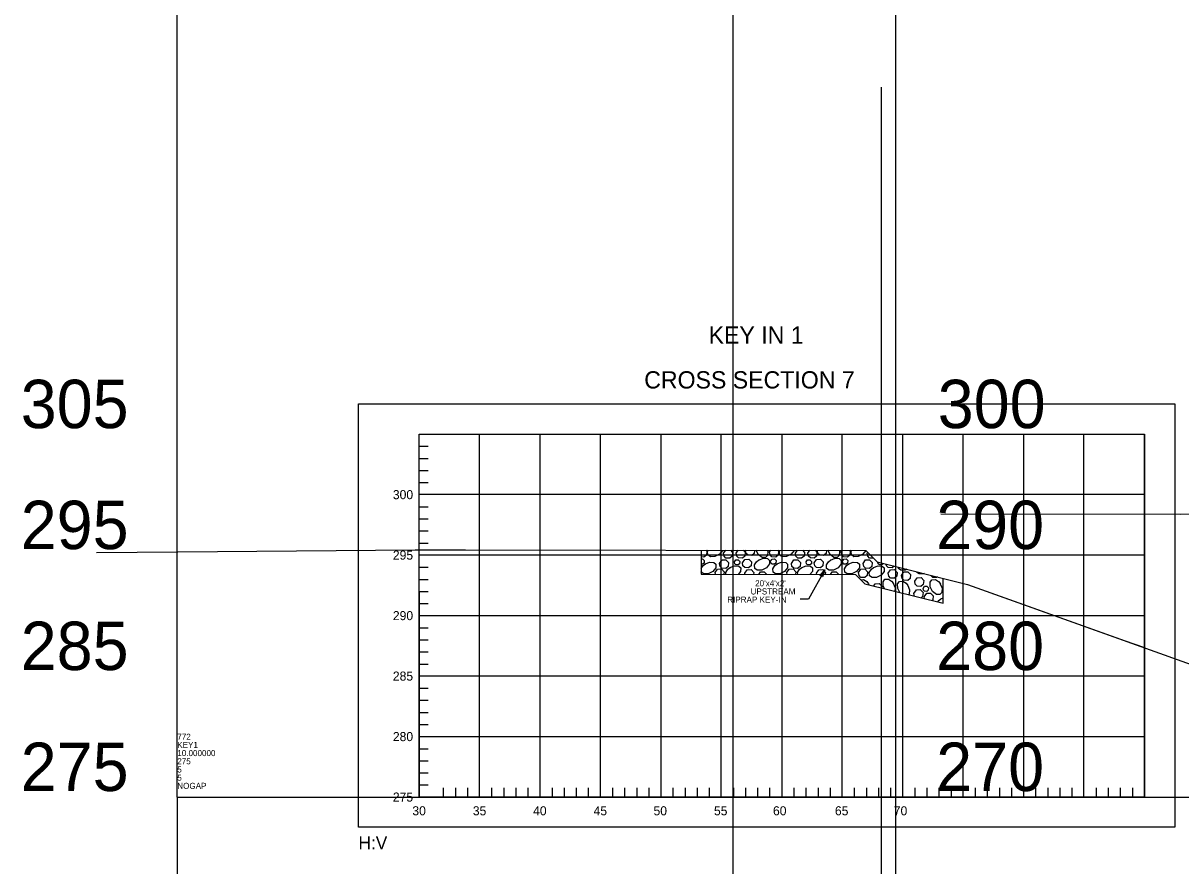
# Model space of a CAD drawing. Extents: x 1578769 to 1579225, y 724002 to 724828.
# Drawn here: x 1578769 to 1578864.8, y 724572.8 to 724642.4 of the extents above; entities that cross this region are included whole.
import ezdxf

# ---------------------------------------------------------------- set-up
doc = ezdxf.new("R2010")
doc.units = 0
for name, color, linetype in [('1', 7, 'Continuous'), ('Default', 7, 'Continuous'), ('Old_Level_1', 7, 'Continuous'), ('Old_Level_41', 7, 'Continuous'), ('Old_Level_42', 7, 'Continuous'), ('R_Exist Surface', 7, 'Continuous'), ('R_Rip-Rap', 7, 'Continuous')]:
    doc.layers.add(name, color=color, linetype=linetype)

msp = doc.modelspace()

# ---------------------------------------------------------------- linework, layer by layer
at = {"layer": '1'}
msp.add_lwpolyline([(1578835.361, 724597.228), (1578833.993, 724594.815), (1578833.307, 724594.815)], dxfattribs=at)
msp.add_lwpolyline([(1578834.961, 724596.765), (1578835.361, 724597.228), (1578835.169, 724596.647)], close=True, dxfattribs=at)
at = {"layer": 'Default'}
for p, q in [((1578781.789, 724578.446), (1578781.789, 724828.446)), ((1578827.766, 724526.976), (1578827.766, 724776.976)), ((1578841.23, 724437.474), (1578841.23, 724687.474)), ((1578840.032, 724387.146), (1578840.032, 724637.146)), ((1578781.789, 724578.446), (1579181.789, 724578.446)), ((1578781.789, 724578.446), (1578781.789, 724328.446))]:
    msp.add_line(p, q, dxfattribs=at)
for points in [[(1578844.95, 724601.856), (1578864.79, 724601.82), (1578874, 724601.865), (1578902.82, 724601.997), (1578906.13, 724598.744), (1578911.44, 724592.793), (1578933.27, 724587.55), (1578934.65, 724587.226), (1578938.86, 724587.197), (1578969.36, 724586.771), (1578979.71, 724588.647), (1578991.4, 724590.556), (1579015.95, 724592.584), (1579047.41, 724595.203), (1579094.57, 724597.518), (1579101.48, 724597.856)], [(1578775.119, 724598.673), (1578781.839, 724598.732), (1578801.469, 724598.898), (1578805.619, 724598.891), (1578838.739, 724598.843), (1578839.679, 724597.89), (1578847.149, 724596.028), (1578873.219, 724586.714), (1578900.509, 724586.288), (1578923.389, 724585.936), (1579003.989, 724586.195), (1579031.649, 724586.167)]]:
    msp.add_lwpolyline(points, dxfattribs=at)
at = {"layer": 'Old_Level_1'}
for points in [[(1578796.789, 724610.946), (1578864.289, 724610.946), (1578864.289, 724575.946), (1578796.789, 724575.946)], [(1578801.789, 724608.446), (1578861.789, 724608.446), (1578861.789, 724578.446), (1578801.789, 724578.446)]]:
    msp.add_lwpolyline(points, close=True, dxfattribs=at)
at = {"layer": 'Old_Level_41'}
for p, q in [((1578806.789, 724578.446), (1578806.789, 724608.446)), ((1578811.789, 724608.446), (1578811.789, 724578.446)), ((1578816.789, 724578.446), (1578816.789, 724608.446)), ((1578821.789, 724608.446), (1578821.789, 724578.446)), ((1578826.789, 724578.446), (1578826.789, 724608.446)), ((1578831.789, 724608.446), (1578831.789, 724578.446)), ((1578836.789, 724578.446), (1578836.789, 724608.446)), ((1578841.789, 724608.446), (1578841.789, 724578.446)), ((1578846.789, 724578.446), (1578846.789, 724608.446)), ((1578851.789, 724608.446), (1578851.789, 724578.446)), ((1578856.789, 724578.446), (1578856.789, 724608.446)), ((1578861.789, 724578.446), (1578861.789, 724608.446)), ((1578801.789, 724595.446), (1578801.789, 724578.446))]:
    msp.add_line(p, q, dxfattribs=at)
for points in [[(1578861.789, 724603.446), (1578801.789, 724603.446)], [(1578861.789, 724598.446), (1578801.789, 724598.446)], [(1578801.789, 724593.446), (1578861.789, 724593.446)], [(1578861.789, 724588.446), (1578801.789, 724588.446)], [(1578801.789, 724583.446), (1578861.789, 724583.446)]]:
    msp.add_lwpolyline(points, dxfattribs=at)
at = {"layer": 'Old_Level_42'}
for p, q in [((1578801.789, 724607.446), (1578802.539, 724607.446)), ((1578801.789, 724606.446), (1578802.539, 724606.446)), ((1578801.789, 724605.446), (1578802.539, 724605.446)), ((1578801.789, 724604.446), (1578802.539, 724604.446)), ((1578801.789, 724602.446), (1578802.539, 724602.446)), ((1578801.789, 724601.446), (1578802.539, 724601.446)), ((1578801.789, 724600.446), (1578802.539, 724600.446)), ((1578801.789, 724599.446), (1578802.539, 724599.446)), ((1578801.789, 724597.446), (1578802.539, 724597.446)), ((1578801.789, 724596.446), (1578802.539, 724596.446)), ((1578801.789, 724595.446), (1578802.539, 724595.446)), ((1578801.789, 724594.446), (1578802.539, 724594.446)), ((1578801.789, 724592.446), (1578802.539, 724592.446)), ((1578801.789, 724591.446), (1578802.539, 724591.446)), ((1578801.789, 724590.446), (1578802.539, 724590.446)), ((1578801.789, 724589.446), (1578802.539, 724589.446)), ((1578801.789, 724587.446), (1578802.539, 724587.446)), ((1578801.789, 724586.446), (1578802.539, 724586.446)), ((1578801.789, 724585.446), (1578802.539, 724585.446)), ((1578801.789, 724584.446), (1578802.539, 724584.446)), ((1578801.789, 724582.446), (1578802.539, 724582.446)), ((1578801.789, 724581.446), (1578802.539, 724581.446)), ((1578801.789, 724580.446), (1578802.539, 724580.446)), ((1578801.789, 724579.446), (1578802.539, 724579.446)), ((1578803.789, 724579.196), (1578803.789, 724578.446)), ((1578804.789, 724579.196), (1578804.789, 724578.446)), ((1578805.789, 724579.196), (1578805.789, 724578.446)), ((1578807.789, 724579.196), (1578807.789, 724578.446)), ((1578808.789, 724579.196), (1578808.789, 724578.446)), ((1578809.789, 724579.196), (1578809.789, 724578.446)), ((1578810.789, 724579.196), (1578810.789, 724578.446)), ((1578812.789, 724579.196), (1578812.789, 724578.446)), ((1578813.789, 724579.196), (1578813.789, 724578.446)), ((1578814.789, 724579.196), (1578814.789, 724578.446)), ((1578815.789, 724579.196), (1578815.789, 724578.446)), ((1578817.789, 724579.196), (1578817.789, 724578.446)), ((1578818.789, 724579.196), (1578818.789, 724578.446)), ((1578819.789, 724579.196), (1578819.789, 724578.446)), ((1578820.789, 724579.196), (1578820.789, 724578.446)), ((1578822.789, 724579.196), (1578822.789, 724578.446)), ((1578823.789, 724579.196), (1578823.789, 724578.446)), ((1578824.789, 724579.196), (1578824.789, 724578.446)), ((1578825.789, 724579.196), (1578825.789, 724578.446)), ((1578827.789, 724579.196), (1578827.789, 724578.446)), ((1578828.789, 724579.196), (1578828.789, 724578.446)), ((1578829.789, 724579.196), (1578829.789, 724578.446)), ((1578830.789, 724579.196), (1578830.789, 724578.446)), ((1578832.789, 724579.196), (1578832.789, 724578.446)), ((1578833.789, 724579.196), (1578833.789, 724578.446)), ((1578834.789, 724579.196), (1578834.789, 724578.446)), ((1578835.789, 724579.196), (1578835.789, 724578.446)), ((1578837.789, 724579.196), (1578837.789, 724578.446)), ((1578838.789, 724579.196), (1578838.789, 724578.446)), ((1578839.789, 724579.196), (1578839.789, 724578.446)), ((1578840.789, 724579.196), (1578840.789, 724578.446)), ((1578842.789, 724579.196), (1578842.789, 724578.446)), ((1578843.789, 724579.196), (1578843.789, 724578.446)), ((1578844.789, 724579.196), (1578844.789, 724578.446)), ((1578845.789, 724579.196), (1578845.789, 724578.446)), ((1578847.789, 724579.196), (1578847.789, 724578.446)), ((1578848.789, 724579.196), (1578848.789, 724578.446)), ((1578849.789, 724579.196), (1578849.789, 724578.446)), ((1578850.789, 724579.196), (1578850.789, 724578.446)), ((1578852.789, 724579.196), (1578852.789, 724578.446)), ((1578853.789, 724579.196), (1578853.789, 724578.446)), ((1578854.789, 724579.196), (1578854.789, 724578.446)), ((1578855.789, 724579.196), (1578855.789, 724578.446)), ((1578857.789, 724579.196), (1578857.789, 724578.446)), ((1578858.789, 724579.196), (1578858.789, 724578.446)), ((1578859.789, 724579.196), (1578859.789, 724578.446)), ((1578860.789, 724579.196), (1578860.789, 724578.446))]:
    msp.add_line(p, q, dxfattribs=at)
at = {"layer": 'R_Exist Surface'}
msp.add_lwpolyline([(1578801.789, 724598.897), (1578805.619, 724598.891), (1578838.739, 724598.843), (1578839.679, 724597.89), (1578847.149, 724596.028), (1578860.184, 724591.371), (1578861.789, 724590.797)], dxfattribs=at)
at = {"layer": 'R_Rip-Rap'}
for p, q in [((1578825.129, 724598.863), (1578825.129, 724596.863)), ((1578826.978, 724598.603), (1578827.159, 724598.86)), ((1578828.019, 724598.615), (1578828.19, 724598.858)), ((1578828.801, 724598.825), (1578828.824, 724598.857)), ((1578830.774, 724598.709), (1578830.876, 724598.854)), ((1578832.914, 724598.603), (1578833.089, 724598.851)), ((1578833.955, 724598.615), (1578834.12, 724598.85)), ((1578834.737, 724598.825), (1578834.754, 724598.849)), ((1578836.71, 724598.709), (1578836.806, 724598.846)), ((1578838.851, 724598.603), (1578838.903, 724598.677)), ((1578826.296, 724596.861), (1578826.268, 724597.004)), ((1578828.74, 724596.858), (1578828.722, 724596.948)), ((1578832.234, 724596.852), (1578832.204, 724597.004)), ((1578834.678, 724596.849), (1578834.658, 724596.948)), ((1578845.129, 724594.47), (1578845.129, 724596.531)), ((1578838.964, 724596.082), (1578838.997, 724595.999)), ((1578842.772, 724595.058), (1578842.727, 724595.288)), ((1578843.609, 724594.849), (1578843.579, 724595.003)), ((1578844.945, 724594.835), (1578845.129, 724594.908))]:
    msp.add_line(p, q, dxfattribs=at)
for points in [[(1578825.509, 724598.862), (1578825.586, 724598.783), (1578825.553, 724598.457), (1578825.354, 724598.292), (1578825.129, 724598.308)], [(1578826.885, 724598.86), (1578826.885, 724598.834), (1578826.635, 724598.514), (1578826.248, 724598.321), (1578825.884, 724598.314), (1578825.679, 724598.46), (1578825.66, 724598.75), (1578825.731, 724598.862)], [(1578827.549, 724598.859), (1578827.726, 724598.676), (1578827.694, 724598.351), (1578827.495, 724598.186), (1578827.177, 724598.209), (1578827.027, 724598.354), (1578826.979, 724598.603)], [(1578828.603, 724598.858), (1578828.766, 724598.688), (1578828.734, 724598.363), (1578828.535, 724598.197), (1578828.217, 724598.22), (1578828.068, 724598.366), (1578828.019, 724598.615)], [(1578829.545, 724598.856), (1578829.516, 724598.573), (1578829.317, 724598.408), (1578828.999, 724598.431), (1578828.85, 724598.576), (1578828.801, 724598.825)], [(1578830.594, 724598.855), (1578830.633, 724598.755), (1578830.603, 724598.409), (1578830.447, 724598.244), (1578830.166, 724598.249), (1578829.846, 724598.499), (1578829.668, 724598.856)], [(1578831.453, 724598.854), (1578831.522, 724598.783), (1578831.489, 724598.457), (1578831.291, 724598.292), (1578830.973, 724598.315), (1578830.823, 724598.46), (1578830.775, 724598.709)], [(1578832.821, 724598.852), (1578832.821, 724598.834), (1578832.571, 724598.514), (1578832.184, 724598.321), (1578831.82, 724598.314), (1578831.615, 724598.46), (1578831.596, 724598.75), (1578831.662, 724598.853)], [(1578833.494, 724598.851), (1578833.662, 724598.676), (1578833.63, 724598.351), (1578833.431, 724598.186), (1578833.113, 724598.209), (1578832.963, 724598.354), (1578832.915, 724598.603)], [(1578834.547, 724598.849), (1578834.703, 724598.688), (1578834.67, 724598.363), (1578834.471, 724598.197), (1578834.153, 724598.22), (1578834.004, 724598.366), (1578833.955, 724598.615)], [(1578835.48, 724598.848), (1578835.452, 724598.573), (1578835.253, 724598.408), (1578834.936, 724598.431), (1578834.786, 724598.576), (1578834.737, 724598.825)], [(1578836.533, 724598.846), (1578836.569, 724598.755), (1578836.539, 724598.409), (1578836.383, 724598.244), (1578836.102, 724598.249), (1578835.782, 724598.499), (1578835.608, 724598.848)], [(1578837.398, 724598.845), (1578837.458, 724598.783), (1578837.426, 724598.457), (1578837.227, 724598.292), (1578836.909, 724598.315), (1578836.759, 724598.46), (1578836.711, 724598.709)], [(1578838.753, 724598.829), (1578838.507, 724598.514), (1578838.12, 724598.321), (1578837.756, 724598.314), (1578837.551, 724598.46), (1578837.532, 724598.75), (1578837.593, 724598.845)], [(1578839.378, 724598.195), (1578839.367, 724598.186), (1578839.049, 724598.209), (1578838.899, 724598.354), (1578838.851, 724598.603)], [(1578825.129, 724598.124), (1578825.244, 724598.13), (1578825.379, 724597.991), (1578825.359, 724597.796), (1578825.24, 724597.697), (1578825.129, 724597.705)], [(1578825.453, 724597.726), (1578825.83, 724597.876), (1578826.177, 724597.846), (1578826.341, 724597.689), (1578826.336, 724597.408), (1578826.086, 724597.088), (1578825.7, 724596.895), (1578825.336, 724596.889), (1578825.131, 724597.035), (1578825.129, 724597.057)], [(1578825.129, 724597.353), (1578825.277, 724597.584), (1578825.468, 724597.736)], [(1578826.648, 724597.763), (1578826.849, 724598.05), (1578827.171, 724598.068), (1578827.395, 724597.836), (1578827.363, 724597.511), (1578827.164, 724597.346), (1578826.846, 724597.369), (1578826.696, 724597.514), (1578826.648, 724597.763)], [(1578827.172, 724596.86), (1578827.161, 724597.02), (1578827.327, 724597.279), (1578827.518, 724597.431)], [(1578827.502, 724597.421), (1578827.88, 724597.571), (1578828.226, 724597.541), (1578828.391, 724597.384), (1578828.386, 724597.103), (1578828.194, 724596.858)], [(1578827.871, 724597.881), (1578827.992, 724598.053), (1578828.186, 724598.064), (1578828.32, 724597.925), (1578828.3, 724597.73), (1578828.181, 724597.631), (1578827.99, 724597.644), (1578827.901, 724597.731), (1578827.871, 724597.881)], [(1578828.532, 724597.807), (1578828.734, 724598.094), (1578829.056, 724598.112), (1578829.28, 724597.88), (1578829.247, 724597.555), (1578829.048, 724597.389), (1578828.731, 724597.412), (1578828.581, 724597.557), (1578828.532, 724597.807)], [(1578829.886, 724598.036), (1578830.263, 724598.186), (1578830.61, 724598.156), (1578830.774, 724597.999), (1578830.769, 724597.718), (1578830.519, 724597.398), (1578830.133, 724597.205), (1578829.768, 724597.199), (1578829.564, 724597.344), (1578829.544, 724597.634), (1578829.71, 724597.894), (1578829.901, 724598.046)], [(1578830.866, 724597.947), (1578830.987, 724598.119), (1578831.18, 724598.13), (1578831.315, 724597.991), (1578831.295, 724597.796), (1578831.176, 724597.697), (1578830.985, 724597.71), (1578830.895, 724597.798), (1578830.866, 724597.947)], [(1578831.389, 724597.726), (1578831.766, 724597.876), (1578832.113, 724597.846), (1578832.277, 724597.689), (1578832.272, 724597.408), (1578832.022, 724597.088), (1578831.636, 724596.895), (1578831.272, 724596.889), (1578831.067, 724597.035), (1578831.047, 724597.325), (1578831.214, 724597.584), (1578831.404, 724597.736)], [(1578832.584, 724597.763), (1578832.785, 724598.05), (1578833.107, 724598.068), (1578833.331, 724597.836), (1578833.299, 724597.511), (1578833.1, 724597.346), (1578832.782, 724597.369), (1578832.632, 724597.514), (1578832.584, 724597.763)], [(1578833.108, 724596.851), (1578833.097, 724597.02), (1578833.263, 724597.279), (1578833.454, 724597.431)], [(1578833.439, 724597.421), (1578833.816, 724597.571), (1578834.162, 724597.541), (1578834.327, 724597.384), (1578834.322, 724597.103), (1578834.124, 724596.85)], [(1578833.807, 724597.881), (1578833.928, 724598.053), (1578834.122, 724598.064), (1578834.256, 724597.925), (1578834.237, 724597.73), (1578834.117, 724597.631), (1578833.926, 724597.644), (1578833.837, 724597.731), (1578833.808, 724597.881)], [(1578834.468, 724597.807), (1578834.67, 724598.094), (1578834.992, 724598.112), (1578835.216, 724597.88), (1578835.183, 724597.555), (1578834.985, 724597.389), (1578834.667, 724597.412), (1578834.517, 724597.557), (1578834.469, 724597.807)], [(1578835.822, 724598.036), (1578836.199, 724598.186), (1578836.546, 724598.156), (1578836.71, 724597.999), (1578836.705, 724597.718), (1578836.455, 724597.398), (1578836.069, 724597.205), (1578835.705, 724597.199), (1578835.5, 724597.344), (1578835.48, 724597.634), (1578835.647, 724597.894), (1578835.837, 724598.046)], [(1578836.802, 724597.947), (1578836.923, 724598.119), (1578837.117, 724598.13), (1578837.251, 724597.991), (1578837.231, 724597.796), (1578837.112, 724597.697), (1578836.921, 724597.71), (1578836.832, 724597.798), (1578836.802, 724597.947)], [(1578837.325, 724597.726), (1578837.702, 724597.876), (1578838.049, 724597.846), (1578838.213, 724597.689), (1578838.208, 724597.408), (1578837.958, 724597.088), (1578837.572, 724596.895), (1578837.208, 724596.889), (1578837.003, 724597.035), (1578836.983, 724597.325), (1578837.15, 724597.584), (1578837.34, 724597.736)], [(1578838.52, 724597.763), (1578838.722, 724598.05), (1578839.043, 724598.068), (1578839.267, 724597.836), (1578839.235, 724597.511), (1578839.036, 724597.346), (1578838.718, 724597.369), (1578838.569, 724597.514), (1578838.52, 724597.763)], [(1578839.375, 724597.421), (1578839.752, 724597.571), (1578840.099, 724597.541), (1578840.263, 724597.384), (1578840.258, 724597.103), (1578840.008, 724596.783), (1578839.622, 724596.59), (1578839.257, 724596.584), (1578839.052, 724596.729), (1578839.033, 724597.02), (1578839.199, 724597.279), (1578839.39, 724597.431)], [(1578840.176, 724597.766), (1578840.173, 724597.73), (1578840.053, 724597.631), (1578839.862, 724597.644), (1578839.773, 724597.731), (1578839.745, 724597.873)], [(1578841.097, 724597.536), (1578840.921, 724597.389), (1578840.603, 724597.412), (1578840.453, 724597.557), (1578840.425, 724597.704)], [(1578842.145, 724597.275), (1578842.005, 724597.205), (1578841.641, 724597.199), (1578841.436, 724597.344), (1578841.428, 724597.454)], [(1578825.129, 724596.863), (1578837.901, 724596.844), (1578838.65, 724596.085), (1578845.129, 724594.47)], [(1578826.268, 724597.004), (1578826.47, 724597.291), (1578826.792, 724597.309), (1578827.016, 724597.077), (1578826.994, 724596.86)], [(1578828.722, 724596.948), (1578828.924, 724597.235), (1578829.246, 724597.253), (1578829.47, 724597.021), (1578829.453, 724596.857)], [(1578829.884, 724596.856), (1578830.026, 724597.059), (1578830.348, 724597.077), (1578830.563, 724596.855)], [(1578832.204, 724597.004), (1578832.406, 724597.291), (1578832.728, 724597.309), (1578832.952, 724597.077), (1578832.929, 724596.851)], [(1578834.658, 724596.948), (1578834.86, 724597.235), (1578835.182, 724597.253), (1578835.406, 724597.021), (1578835.388, 724596.848)], [(1578835.814, 724596.847), (1578835.962, 724597.059), (1578836.284, 724597.077), (1578836.507, 724596.846)], [(1578838.14, 724597.004), (1578838.342, 724597.291), (1578838.664, 724597.309), (1578838.888, 724597.077), (1578838.855, 724596.752), (1578838.657, 724596.587), (1578838.339, 724596.61), (1578838.189, 724596.755), (1578838.14, 724597.004)], [(1578838.332, 724596.408), (1578838.563, 724596.423), (1578838.822, 724596.257), (1578838.974, 724596.066)], [(1578840.286, 724595.677), (1578840.183, 724595.883), (1578840.177, 724596.248), (1578840.322, 724596.453), (1578840.612, 724596.472), (1578840.872, 724596.306), (1578841.024, 724596.115)], [(1578840.594, 724596.948), (1578840.796, 724597.235), (1578841.118, 724597.253), (1578841.342, 724597.021), (1578841.309, 724596.696), (1578841.11, 724596.53), (1578840.793, 724596.553), (1578840.643, 724596.698), (1578840.594, 724596.948)], [(1578841.697, 724596.772), (1578841.899, 724597.059), (1578842.221, 724597.077), (1578842.444, 724596.845), (1578842.412, 724596.52), (1578842.213, 724596.354), (1578841.895, 724596.378), (1578841.746, 724596.523), (1578841.697, 724596.772)], [(1578842.783, 724596.284), (1578842.985, 724596.571), (1578843.307, 724596.589), (1578843.531, 724596.357), (1578843.498, 724596.032), (1578843.299, 724595.867), (1578842.981, 724595.89), (1578842.832, 724596.035), (1578842.783, 724596.284)], [(1578843.561, 724596.922), (1578843.508, 724596.895), (1578843.144, 724596.889), (1578842.939, 724597.035), (1578842.936, 724597.078)], [(1578844.9, 724596.082), (1578845.05, 724595.704), (1578845.02, 724595.358), (1578844.863, 724595.193), (1578844.582, 724595.198), (1578844.263, 724595.448), (1578844.069, 724595.835), (1578844.063, 724596.199), (1578844.209, 724596.404), (1578844.499, 724596.423), (1578844.758, 724596.257), (1578844.91, 724596.066)], [(1578844.665, 724596.647), (1578844.593, 724596.587), (1578844.275, 724596.61), (1578844.125, 724596.755), (1578844.12, 724596.783)], [(1578839.398, 724595.899), (1578839.528, 724596.083), (1578839.85, 724596.101), (1578840.074, 724595.869), (1578840.061, 724595.733)], [(1578841.014, 724596.13), (1578841.164, 724595.753), (1578841.139, 724595.465)], [(1578841.547, 724595.363), (1578841.379, 724595.7), (1578841.372, 724596.065), (1578841.518, 724596.27), (1578841.808, 724596.289), (1578842.067, 724596.123), (1578842.219, 724595.932)], [(1578842.21, 724595.947), (1578842.359, 724595.57), (1578842.329, 724595.223), (1578842.287, 724595.179)], [(1578842.727, 724595.288), (1578842.928, 724595.575), (1578843.25, 724595.593), (1578843.474, 724595.361), (1578843.442, 724595.036), (1578843.307, 724594.924)], [(1578843.476, 724595.696), (1578843.597, 724595.868), (1578843.79, 724595.88), (1578843.925, 724595.74), (1578843.905, 724595.545), (1578843.786, 724595.446), (1578843.595, 724595.46), (1578843.505, 724595.547), (1578843.476, 724595.696)], [(1578843.579, 724595.003), (1578843.781, 724595.29), (1578844.102, 724595.308), (1578844.326, 724595.076), (1578844.294, 724594.751), (1578844.227, 724594.695)], [(1578844.696, 724594.578), (1578844.77, 724594.692), (1578844.96, 724594.844)]]:
    msp.add_lwpolyline(points, dxfattribs=at)

# ---------------------------------------------------------------- texts
at = {"layer": '1'}
for s, height, p in [('300', 0.75, (1578799.623, 724603.071)), ('295', 0.75, (1578799.623, 724598.071)), ("20'x4'x2'", 0.5, (1578829.589, 724595.874)), ('UPSTREAM', 0.5, (1578829.211, 724595.196)), ('RIPRAP KEY-IN', 0.5, (1578827.278, 724594.519)), ('290', 0.75, (1578799.623, 724593.071)), ('285', 0.75, (1578799.623, 724588.071)), ('280', 0.75, (1578799.623, 724583.071)), ('275', 0.75, (1578799.623, 724578.071)), ('30', 0.75, (1578801.235, 724576.936)), ('35', 0.75, (1578806.235, 724576.936)), ('40', 0.75, (1578811.223, 724576.936)), ('45', 0.75, (1578816.223, 724576.936)), ('50', 0.75, (1578821.182, 724576.936)), ('55', 0.75, (1578826.182, 724576.936)), ('60', 0.75, (1578831.064, 724576.936)), ('65', 0.75, (1578836.188, 724576.936)), ('70', 0.75, (1578841.058, 724576.936))]:
    msp.add_text(s, height=height, dxfattribs=at).set_placement(p)
at = {"layer": 'Default'}
for s, height, p in [('     305', 4, (1578761.407, 724608.946)), ('     300', 4, (1578837.259, 724608.946)), ('     295', 4, (1578761.407, 724598.946)), ('     295', 4, (1578761.407, 724598.946)), ('     290', 4, (1578837.133, 724598.946)), ('     285', 4, (1578761.407, 724588.946)), ('     285', 4, (1578761.407, 724588.946)), ('     280', 4, (1578837.133, 724588.946)), ('     275', 4, (1578761.407, 724578.946)), ('     275', 4, (1578761.407, 724578.946)), ('772', 0.5, (1578781.789, 724583.186)), ('KEY1', 0.5, (1578781.789, 724582.509)), ('     270', 4, (1578837.133, 724578.946)), ('10.000000', 0.5, (1578781.789, 724581.832)), ('275', 0.5, (1578781.789, 724581.155)), ('5', 0.5, (1578781.789, 724580.477)), ('5', 0.5, (1578781.789, 724579.8)), ('NOGAP', 0.5, (1578781.789, 724579.123))]:
    msp.add_text(s, height=height, dxfattribs=at).set_placement(p)
at = {"layer": 'Old_Level_1'}
for s, height, p in [('KEY IN 1', 1.4286, (1578825.739, 724615.924)), ('CROSS SECTION 7', 1.42857, (1578820.413, 724612.223)), ('H:V', 1.0714, (1578796.774, 724574.129))]:
    msp.add_text(s, height=height, dxfattribs=at).set_placement(p)

doc.saveas('drawing.dxf')
